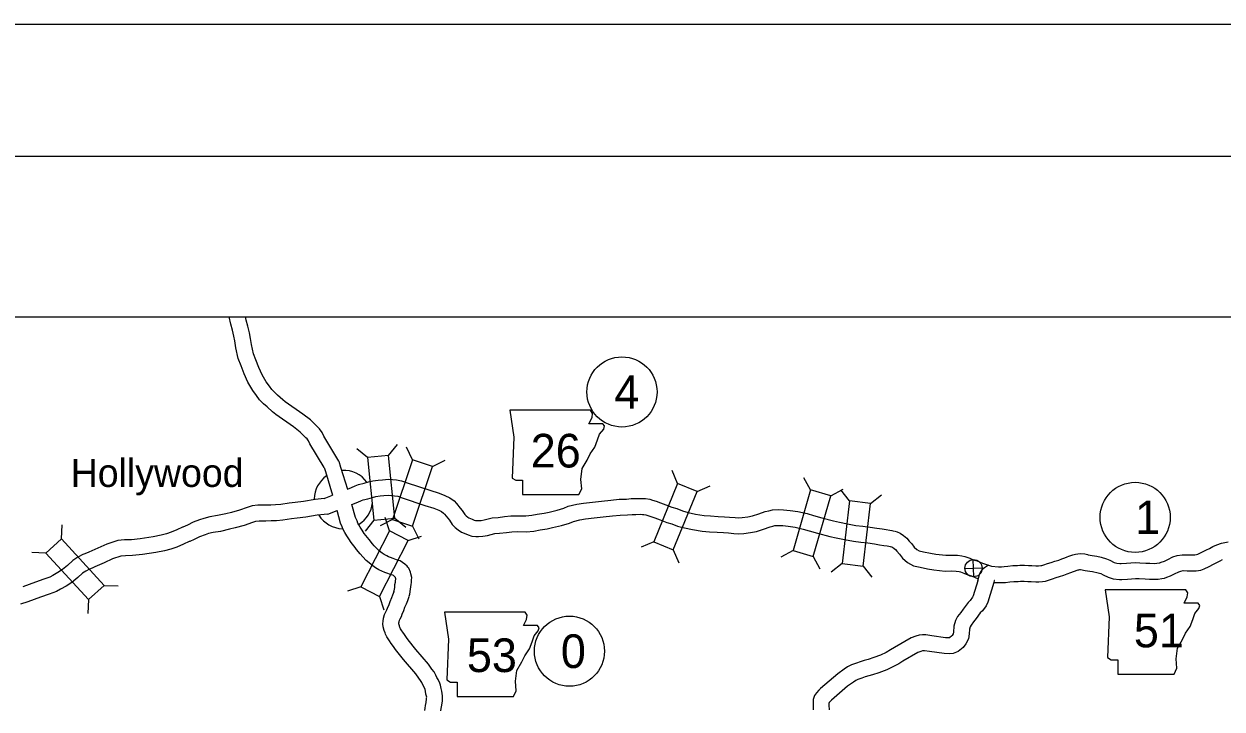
# Model space of a CAD drawing. Extents: x 1369979 to 1371646, y 379997 to 381064.
# Drawn here: x 1370145.5 to 1370321.9, y 380963.2 to 381064.1 of the extents above; entities that cross this region are included whole.
import ezdxf

# ---------------------------------------------------------------- set-up
doc = ezdxf.new("R2010")
doc.units = 0
for name, color, linetype in [('R_Border', 7, 'Continuous'), ('R_Border Notes', 7, 'Continuous'), ('R_No Plot', 7, 'Continuous')]:
    doc.layers.add(name, color=color, linetype=linetype)

msp = doc.modelspace()

# ---------------------------------------------------------------- linework, layer by layer
at = {"layer": 'R_Border'}
msp.add_line((1370040.95, 381044.6), (1371621.85, 381044.6), dxfattribs=at)
at = {"layer": 'R_Border Notes'}
for p, q in [((1370196.09, 381000.26), (1370194.49, 381001.56)), ((1370199.17, 381000.57), (1370200.47, 381002.17)), ((1370202.71, 380999.94), (1370201.79, 381001.79)), ((1370205.65, 380998.96), (1370207.49, 380999.88)), ((1370241.73, 380996.44), (1370240.93, 380998.34)), ((1370244.6, 380995.27), (1370246.5, 380996.08)), ((1370261.31, 380995.48), (1370260.31, 380997.28)), ((1370264.28, 380994.61), (1370266.09, 380995.61)), ((1370267.05, 380993.87), (1370265.77, 380995.49)), ((1370270.12, 380993.51), (1370271.74, 380994.79)), ((1370197.02, 380991.03), (1370195.71, 380989.43)), ((1370199.76, 380991.14), (1370197.92, 380990.22)), ((1370199.31, 380989.47), (1370198.68, 380991.43)), ((1370200.1, 380991.34), (1370201.7, 380990.03)), ((1370151.01, 380988.28), (1370151.1, 380990.35)), ((1370202.7, 380990.16), (1370203.61, 380988.31)), ((1370202.06, 380988.05), (1370204.02, 380988.68)), ((1370238.24, 380987.84), (1370236.34, 380987.04)), ((1370148.72, 380986.2), (1370146.66, 380986.29)), ((1370241.1, 380986.68), (1370241.91, 380984.78)), ((1370258.73, 380986.56), (1370256.92, 380985.57)), ((1370261.7, 380985.7), (1370262.69, 380983.89)), ((1370285.33, 380982.7), (1370285.27, 380985.24)), ((1370265.96, 380984.66), (1370264.34, 380983.38)), ((1370269.03, 380984.29), (1370270.31, 380982.67)), ((1370284.03, 380983.94), (1370286.57, 380984)), ((1370157.27, 380981.44), (1370159.34, 380981.35)), ((1370195.07, 380981.21), (1370193.11, 380980.58)), ((1370154.99, 380979.35), (1370154.9, 380977.29)), ((1370197.82, 380979.8), (1370198.45, 380977.83))]:
    msp.add_line(p, q, dxfattribs=at)
for points in [[(1370189.69, 380998.78), (1370187.6, 381002.28), (1370187.38, 381002.71), (1370187.17, 381002.99), (1370187.01, 381003.18), (1370186.66, 381003.52), (1370186.15, 381004.01), (1370185.16, 381004.76), (1370182.55, 381006.6), (1370182.07, 381006.98), (1370181.28, 381007.7), (1370180.76, 381008.16), (1370180.18, 381008.74), (1370179.72, 381009.38), (1370179.2, 381010.1), (1370178.46, 381011.37), (1370177.92, 381012.6), (1370177.46, 381013.77), (1370177.04, 381014.81), (1370176.66, 381016.42), (1370176.51, 381017.43), (1370176.39, 381018.14), (1370176.17, 381019.02), (1370175.95, 381019.89), (1370175.68, 381020.95)], [(1370191.87, 380999.71), (1370189.65, 381003.42), (1370189.37, 381003.96), (1370189, 381004.46), (1370188.71, 381004.79), (1370188.28, 381005.2), (1370187.68, 381005.79), (1370186.54, 381006.65), (1370183.96, 381008.47), (1370183.59, 381008.77), (1370182.84, 381009.44), (1370182.37, 381009.86), (1370181.97, 381010.27), (1370181.62, 381010.75), (1370181.17, 381011.38), (1370180.55, 381012.43), (1370180.09, 381013.5), (1370179.64, 381014.63), (1370179.28, 381015.52), (1370178.97, 381016.87), (1370178.83, 381017.8), (1370178.68, 381018.62), (1370178.44, 381019.59), (1370178.22, 381020.46), (1370178.1, 381020.95)], [(1370191.87, 380999.71), (1370192.1, 380998.85), (1370193.12, 380995.59)], [(1370189.69, 380998.78), (1370189.86, 380998.19), (1370190.93, 380994.72)], [(1370193.12, 380995.59), (1370193.7, 380995.83), (1370194.23, 380996.09), (1370194.72, 380996.28), (1370195.56, 380996.48), (1370196.23, 380996.66), (1370196.85, 380996.82), (1370197.62, 380996.93), (1370198.26, 380996.99), (1370199.17, 380997.06), (1370200.34, 380996.96), (1370201.09, 380996.83), (1370201.93, 380996.54), (1370205.26, 380995.43), (1370206.63, 380994.99), (1370207.47, 380994.66), (1370208.17, 380994.34), (1370208.81, 380993.86), (1370209.19, 380993.49), (1370209.7, 380992.82), (1370210.03, 380992.44), (1370210.4, 380991.87), (1370210.59, 380991.67), (1370210.83, 380991.47), (1370210.98, 380991.37), (1370211.47, 380991.18), (1370211.76, 380991.05), (1370211.96, 380990.99), (1370212.06, 380990.97), (1370212.28, 380990.99), (1370212.81, 380991), (1370213.25, 380991.09), (1370214.44, 380991.4), (1370215.31, 380991.44), (1370216.25, 380991.56), (1370217.18, 380991.66), (1370218.1, 380991.69), (1370219.36, 380991.69), (1370220.26, 380991.76), (1370221.07, 380991.91), (1370222.08, 380992.09), (1370222.81, 380992.23), (1370224, 380992.52), (1370224.99, 380992.82), (1370225.63, 380993.1), (1370226.91, 380993.4), (1370227.86, 380993.54), (1370229.18, 380993.69), (1370230.52, 380993.85), (1370231.9, 380994), (1370233.14, 380994.12), (1370234.2, 380994.15), (1370234.91, 380994.22), (1370235.53, 380994.24), (1370236.32, 380994.25), (1370236.64, 380994.23), (1370237, 380994.23), (1370237.63, 380994.11), (1370238.04, 380993.98), (1370238.57, 380993.81), (1370239.19, 380993.58), (1370239.98, 380993.29), (1370240.89, 380992.94), (1370241.63, 380992.74), (1370242.47, 380992.4), (1370243.28, 380992.19), (1370244.37, 380991.94), (1370245.62, 380991.73), (1370246.58, 380991.66), (1370247.7, 380991.6), (1370248.64, 380991.54), (1370249.39, 380991.49), (1370250.19, 380991.43), (1370250.67, 380991.4), (1370251.24, 380991.43), (1370252.09, 380991.55), (1370252.76, 380991.67), (1370253.67, 380991.96), (1370254.64, 380992.29), (1370255.15, 380992.43), (1370255.71, 380992.57), (1370256.55, 380992.59), (1370257.34, 380992.58), (1370258.3, 380992.48), (1370259.45, 380992.33), (1370260.83, 380992), (1370261.76, 380991.73), (1370262.98, 380991.38), (1370264.69, 380990.92), (1370265.56, 380990.72), (1370266.73, 380990.51), (1370267.99, 380990.27), (1370269, 380990.15), (1370270.06, 380990.01), (1370271.06, 380989.87), (1370271.83, 380989.74), (1370272.45, 380989.65), (1370272.96, 380989.57), (1370273.28, 380989.52), (1370273.61, 380989.44)], [(1370189.67, 380994.23), (1370188.35, 380994.09), (1370186.65, 380993.79), (1370185.41, 380993.64), (1370184.55, 380993.54), (1370183.32, 380993.35), (1370182.53, 380993.28), (1370181.85, 380993.26), (1370181.09, 380993.26), (1370180.55, 380993.26), (1370179.94, 380993.25), (1370179.07, 380993.13), (1370178.37, 380992.9), (1370177.22, 380992.49), (1370176.02, 380992.19), (1370175.19, 380991.98), (1370174, 380991.7), (1370172.87, 380991.54), (1370171.97, 380991.3), (1370171.35, 380991.08), (1370170.41, 380990.73), (1370169.58, 380990.32), (1370168.88, 380990.03), (1370168.81, 380990)], [(1370189.67, 380994.23), (1370190.93, 380994.72)], [(1370193.78, 380993.33), (1370194.66, 380993.69), (1370195.18, 380993.94), (1370195.42, 380994.04), (1370196.14, 380994.2), (1370196.82, 380994.39), (1370197.31, 380994.51), (1370197.91, 380994.6), (1370198.47, 380994.66), (1370199.16, 380994.71), (1370200.04, 380994.63), (1370200.51, 380994.55), (1370201.18, 380994.32), (1370204.53, 380993.2), (1370205.85, 380992.78), (1370206.56, 380992.5), (1370206.96, 380992.32), (1370207.27, 380992.09), (1370207.43, 380991.93), (1370207.89, 380991.33), (1370208.16, 380991.02), (1370208.55, 380990.41), (1370209, 380989.94), (1370209.43, 380989.6), (1370209.89, 380989.28), (1370210.55, 380989.03), (1370210.91, 380988.86), (1370211.45, 380988.69), (1370212, 380988.62), (1370212.41, 380988.65), (1370213.05, 380988.66), (1370213.76, 380988.8), (1370214.8, 380989.07), (1370215.52, 380989.1), (1370216.52, 380989.24), (1370217.34, 380989.32), (1370218.14, 380989.35), (1370219.45, 380989.34), (1370220.56, 380989.43), (1370221.48, 380989.6), (1370222.52, 380989.78), (1370223.31, 380989.95), (1370224.61, 380990.25), (1370225.8, 380990.61), (1370226.38, 380990.86), (1370227.35, 380991.1), (1370228.16, 380991.21), (1370229.45, 380991.36), (1370230.79, 380991.52), (1370232.14, 380991.67), (1370233.29, 380991.78), (1370234.34, 380991.81), (1370235.05, 380991.88), (1370235.58, 380991.89), (1370236.28, 380991.9), (1370236.57, 380991.89), (1370236.75, 380991.89), (1370237.06, 380991.83), (1370237.34, 380991.74), (1370237.81, 380991.59), (1370238.38, 380991.38), (1370239.16, 380991.1), (1370240.16, 380990.71), (1370240.88, 380990.51), (1370241.73, 380990.17), (1370242.73, 380989.91), (1370243.92, 380989.64), (1370245.33, 380989.41), (1370246.43, 380989.32), (1370247.56, 380989.26), (1370248.48, 380989.2), (1370249.23, 380989.16), (1370250.03, 380989.09), (1370250.65, 380989.05), (1370251.46, 380989.09), (1370252.47, 380989.24), (1370253.33, 380989.39), (1370254.4, 380989.73), (1370255.34, 380990.05), (1370255.75, 380990.17), (1370256.03, 380990.24), (1370256.56, 380990.25), (1370257.21, 380990.24), (1370258.03, 380990.15), (1370259.02, 380990.03), (1370260.23, 380989.73), (1370261.12, 380989.48), (1370262.35, 380989.12), (1370264.12, 380988.64), (1370265.09, 380988.42), (1370266.3, 380988.2), (1370267.63, 380987.95), (1370268.7, 380987.82), (1370269.74, 380987.69), (1370270.71, 380987.55), (1370271.47, 380987.42), (1370272.1, 380987.33), (1370272.61, 380987.25), (1370272.83, 380987.22), (1370273.09, 380987.16)], [(1370190.23, 380991.94), (1370191.59, 380992.46)], [(1370199.96, 380980.49), (1370200, 380980.62), (1370200.07, 380981.14), (1370200.11, 380981.56), (1370200.18, 380981.91), (1370200.2, 380982.13), (1370200.22, 380982.35), (1370200.22, 380982.38), (1370200.18, 380982.57), (1370200.17, 380982.62), (1370200.16, 380982.63), (1370200.11, 380982.72), (1370199.89, 380982.87), (1370199.81, 380982.92), (1370199.57, 380983), (1370199.08, 380983.18), (1370198.63, 380983.32), (1370198.16, 380983.52), (1370197.75, 380983.73), (1370197.25, 380984.04), (1370196.87, 380984.31), (1370196.3, 380984.74), (1370195.88, 380985.12), (1370195.36, 380985.62), (1370194.97, 380986.08), (1370194.47, 380986.73), (1370194.23, 380987.01), (1370193.65, 380987.75), (1370193.31, 380988.31), (1370193.03, 380988.72), (1370192.72, 380989.24), (1370192.5, 380989.68), (1370192.36, 380990.04), (1370192.09, 380990.62), (1370191.59, 380992.46)], [(1370202.22, 380979.84), (1370202.3, 380980.14), (1370202.4, 380980.88), (1370202.43, 380981.22), (1370202.5, 380981.56), (1370202.53, 380981.88), (1370202.56, 380982.2), (1370202.58, 380982.61), (1370202.46, 380983.15), (1370202.39, 380983.39), (1370202.15, 380983.96), (1370202, 380984.12), (1370201.9, 380984.27), (1370201.58, 380984.56), (1370201.23, 380984.79), (1370200.89, 380985.04), (1370200.33, 380985.22), (1370199.84, 380985.39), (1370199.45, 380985.52), (1370199.15, 380985.65), (1370198.91, 380985.77), (1370198.54, 380986), (1370198.25, 380986.2), (1370197.8, 380986.54), (1370197.48, 380986.83), (1370197.06, 380987.24), (1370196.78, 380987.56), (1370196.3, 380988.19), (1370196.06, 380988.48), (1370195.58, 380989.08), (1370195.29, 380989.58), (1370195, 380989.99), (1370194.77, 380990.37), (1370194.65, 380990.62), (1370194.53, 380990.94), (1370194.3, 380991.43), (1370193.78, 380993.33)], [(1370190.23, 380991.94), (1370188.68, 380991.77), (1370187, 380991.47), (1370185.69, 380991.32), (1370184.86, 380991.22), (1370183.61, 380991.03), (1370182.67, 380990.94), (1370181.88, 380990.92), (1370181.1, 380990.91), (1370180.56, 380990.91), (1370180.11, 380990.91), (1370179.6, 380990.84), (1370179.13, 380990.69), (1370177.9, 380990.24), (1370176.59, 380989.92), (1370175.75, 380989.7), (1370174.43, 380989.39), (1370173.34, 380989.24), (1370172.66, 380989.06), (1370172.16, 380988.88), (1370171.34, 380988.57), (1370170.54, 380988.18), (1370169.92, 380987.92)], [(1370168.81, 380990), (1370168, 380989.63), (1370167.16, 380989.26), (1370166.46, 380989.02), (1370165.67, 380988.83), (1370164.52, 380988.6), (1370162.6, 380988.31), (1370161.31, 380988.16), (1370160.28, 380988.12), (1370159.31, 380988.03), (1370157.67, 380987.52), (1370156.35, 380986.9), (1370155.02, 380986.32), (1370154.45, 380986.09)], [(1370273.7, 380989.42), (1370274.08, 380989.31), (1370274.48, 380989.11), (1370275.01, 380988.79), (1370275.48, 380988.39), (1370275.84, 380987.97), (1370276.2, 380987.53), (1370276.57, 380987.07), (1370276.93, 380986.74), (1370277.31, 380986.53), (1370277.95, 380986.39), (1370278.96, 380986.17), (1370279.76, 380986.04), (1370281.22, 380985.89), (1370282.1, 380985.9), (1370282.95, 380985.87), (1370283.6, 380985.79), (1370284.04, 380985.68), (1370284.75, 380985.44), (1370285.26, 380985.22), (1370285.84, 380985.05), (1370286.61, 380984.69)], [(1370169.92, 380987.92), (1370169.81, 380987.88), (1370168.96, 380987.49), (1370168.01, 380987.07), (1370167.11, 380986.77), (1370166.17, 380986.54), (1370164.92, 380986.29), (1370162.92, 380985.99), (1370161.49, 380985.82), (1370160.42, 380985.78), (1370159.77, 380985.72), (1370158.53, 380985.33), (1370157.31, 380984.76), (1370155.93, 380984.16), (1370155.51, 380983.99)], [(1370273.01, 380987.18), (1370273.23, 380987.11), (1370273.37, 380987.04), (1370273.64, 380986.89), (1370273.8, 380986.74), (1370274.03, 380986.47), (1370274.38, 380986.04), (1370274.86, 380985.46), (1370275.56, 380984.82), (1370276.46, 380984.33), (1370277.44, 380984.1), (1370278.52, 380983.86), (1370279.46, 380983.71), (1370281.11, 380983.55), (1370282.07, 380983.56), (1370282.76, 380983.53), (1370283.19, 380983.48), (1370283.4, 380983.43), (1370283.89, 380983.26), (1370284.45, 380983.01), (1370285.02, 380982.84), (1370285.99, 380982.4)], [(1370288.99, 380984.18), (1370289, 380984.18), (1370289.42, 380984.19), (1370289.81, 380984.21), (1370290.37, 380984.28), (1370291.08, 380984.37), (1370291.8, 380984.37), (1370292.14, 380984.39), (1370292.8, 380984.39), (1370293.4, 380984.36), (1370293.88, 380984.34), (1370294.5, 380984.31), (1370294.86, 380984.32), (1370295.2, 380984.34), (1370295.36, 380984.37), (1370295.64, 380984.45), (1370296.19, 380984.64), (1370296.72, 380984.82), (1370297.25, 380984.99), (1370297.87, 380985.17), (1370298.31, 380985.33), (1370298.76, 380985.49), (1370299.07, 380985.62), (1370299.34, 380985.75), (1370299.9, 380985.92), (1370300.1, 380985.97), (1370300.34, 380986.04), (1370300.67, 380986.09), (1370301.06, 380986.13), (1370301.71, 380986.06), (1370302.09, 380985.96), (1370302.2, 380985.93), (1370302.76, 380985.84), (1370303.11, 380985.8), (1370303.44, 380985.76), (1370304.09, 380985.61), (1370304.87, 380985.36), (1370305.36, 380985.14), (1370306.01, 380984.83), (1370306.39, 380984.7), (1370306.84, 380984.65), (1370307.02, 380984.66), (1370307.81, 380984.69), (1370309.08, 380984.8), (1370309.78, 380984.77), (1370310.68, 380984.72), (1370311.27, 380984.7), (1370311.92, 380984.68), (1370312.3, 380984.7), (1370312.62, 380984.74), (1370312.75, 380984.77), (1370312.94, 380984.84), (1370313.4, 380985.02), (1370313.89, 380985.24), (1370314.64, 380985.62), (1370315.27, 380985.82), (1370316, 380985.95), (1370316.8, 380985.94), (1370317.5, 380985.93), (1370317.9, 380985.91), (1370318.15, 380985.96), (1370318.34, 380986.03), (1370318.92, 380986.32), (1370319.59, 380986.67), (1370320.05, 380986.89), (1370320.55, 380987.16), (1370321.11, 380987.43), (1370321.8, 380987.64), (1370322.8, 380987.85)], [(1370154.45, 380986.09), (1370154.15, 380985.96), (1370153.41, 380985.59), (1370152.67, 380985.11), (1370151.88, 380984.38), (1370151.15, 380983.77), (1370150.47, 380983.34), (1370149.73, 380982.9), (1370149.31, 380982.67), (1370148.4, 380982.33), (1370147.16, 380981.89), (1370145.3, 380981.24)], [(1370288.29, 380981.86), (1370288.97, 380981.84), (1370289.5, 380981.84), (1370290.03, 380981.87), (1370290.67, 380981.96), (1370291.23, 380982.03), (1370291.86, 380982.03), (1370292.2, 380982.05), (1370292.74, 380982.05), (1370293.28, 380982.02), (1370293.78, 380981.99), (1370294.47, 380981.97), (1370294.94, 380981.97), (1370295.47, 380982.01), (1370295.89, 380982.08), (1370296.36, 380982.22), (1370296.95, 380982.42), (1370297.46, 380982.59), (1370297.95, 380982.75), (1370298.61, 380982.95), (1370299.1, 380983.13), (1370299.61, 380983.31), (1370300.01, 380983.48), (1370300.17, 380983.55), (1370300.54, 380983.67), (1370300.72, 380983.71), (1370300.83, 380983.74), (1370300.96, 380983.76), (1370301.07, 380983.77), (1370301.28, 380983.75), (1370301.49, 380983.69), (1370301.74, 380983.63), (1370302.44, 380983.52), (1370302.82, 380983.48), (1370303.03, 380983.45), (1370303.47, 380983.35), (1370304.03, 380983.17), (1370304.38, 380983.01), (1370305.12, 380982.65), (1370305.88, 380982.4), (1370306.78, 380982.29), (1370307.15, 380982.32), (1370307.96, 380982.35), (1370309.13, 380982.45), (1370309.68, 380982.43), (1370310.57, 380982.38), (1370311.19, 380982.36), (1370311.94, 380982.34), (1370312.49, 380982.36), (1370313.01, 380982.43), (1370313.4, 380982.51), (1370313.75, 380982.64), (1370314.32, 380982.86), (1370314.9, 380983.13), (1370315.53, 380983.44), (1370315.85, 380983.54), (1370316.19, 380983.61), (1370316.75, 380983.6), (1370317.43, 380983.58), (1370318.07, 380983.56), (1370318.75, 380983.68), (1370319.28, 380983.87), (1370319.99, 380984.24), (1370320.63, 380984.57), (1370321.12, 380984.81), (1370321.62, 380985.07), (1370321.96, 380985.24)], [(1370155.51, 380983.99), (1370155.13, 380983.83), (1370154.59, 380983.55), (1370154.11, 380983.25), (1370153.43, 380982.62), (1370152.54, 380981.88), (1370151.69, 380981.34), (1370150.88, 380980.86), (1370150.28, 380980.54), (1370149.21, 380980.13), (1370147.94, 380979.68), (1370146.05, 380979.01), (1370144.96, 380978.66)], [(1370287.51, 380984.42), (1370286.94, 380984.02), (1370286.73, 380983.87), (1370286.49, 380983.64), (1370286.3, 380983.34), (1370286.13, 380983), (1370285.9, 380982.05)], [(1370286.61, 380984.69), (1370287.96, 380984.29)], [(1370287.96, 380984.29), (1370288.99, 380984.18)], [(1370285.92, 380982.11), (1370285.24, 380979.88), (1370285.14, 380979.68), (1370284.81, 380979.22), (1370284.52, 380978.93), (1370283.79, 380977.96), (1370283.43, 380977.46), (1370282.96, 380976.86), (1370282.64, 380976.26), (1370282.39, 380975.42), (1370282.33, 380974.56), (1370282.29, 380974.32), (1370282.17, 380974.08), (1370282.06, 380973.94), (1370281.82, 380973.75), (1370281.76, 380973.73), (1370281.68, 380973.72), (1370281.17, 380973.73), (1370279.18, 380974.03), (1370278.28, 380974.15), (1370277.79, 380974.16), (1370277.32, 380974.11), (1370276.81, 380973.95), (1370276.11, 380973.7), (1370273.67, 380972.3), (1370273.08, 380971.93), (1370272.44, 380971.58), (1370271.62, 380971.18), (1370270.6, 380970.8), (1370269.78, 380970.54), (1370269.22, 380970.37), (1370268.62, 380970.19), (1370268.07, 380970.01), (1370267.33, 380969.74), (1370266.76, 380969.46), (1370266.25, 380969.1), (1370265.31, 380968.44), (1370262.77, 380966.24), (1370262.52, 380966), (1370262.17, 380965.64), (1370261.88, 380965.25), (1370261.71, 380964.64), (1370261.67, 380964.14), (1370261.68, 380963.76), (1370261.69, 380963.14)], [(1370288.29, 380981.86), (1370287.42, 380978.98), (1370287.14, 380978.45), (1370286.6, 380977.7), (1370286.29, 380977.39), (1370285.67, 380976.56), (1370285.3, 380976.05), (1370284.93, 380975.58), (1370284.82, 380975.36), (1370284.71, 380975), (1370284.67, 380974.29), (1370284.54, 380973.58), (1370284.16, 380972.83), (1370283.76, 380972.29), (1370283.02, 380971.7), (1370282.28, 380971.41), (1370281.73, 380971.38), (1370280.97, 380971.39), (1370278.84, 380971.71), (1370278.1, 380971.81), (1370277.91, 380971.82), (1370277.8, 380971.8), (1370277.54, 380971.73), (1370277.1, 380971.56), (1370274.88, 380970.3), (1370274.28, 380969.91), (1370273.51, 380969.5), (1370272.55, 380969.03), (1370271.37, 380968.58), (1370270.45, 380968.29), (1370269.89, 380968.13), (1370269.33, 380967.96), (1370268.84, 380967.8), (1370268.25, 380967.58), (1370267.96, 380967.44), (1370267.61, 380967.19), (1370266.75, 380966.59), (1370264.37, 380964.53), (1370264.2, 380964.36), (1370264.03, 380964.18), (1370264.02, 380964.07), (1370264.02, 380963.79), (1370264.03, 380963.14)], [(1370288.4, 380982.18), (1370288.34, 380982.14), (1370288.27, 380981.86)], [(1370204.49, 380963.03), (1370204.54, 380963.35), (1370204.62, 380963.75), (1370204.69, 380964.18), (1370204.76, 380964.74), (1370204.77, 380964.87), (1370204.78, 380964.96), (1370204.68, 380965.43), (1370204.61, 380965.89), (1370204.57, 380966.12), (1370204.57, 380966.12), (1370204.4, 380966.48), (1370204.21, 380966.8), (1370204.06, 380967.13), (1370203.89, 380967.42), (1370203.64, 380967.77), (1370203.2, 380968.41), (1370201.38, 380970.52), (1370200.18, 380972.01), (1370199.89, 380972.42), (1370199.56, 380972.89), (1370199.32, 380973.26), (1370199.2, 380973.43), (1370198.92, 380973.87), (1370198.72, 380974.26), (1370198.65, 380974.46), (1370198.53, 380974.79), (1370198.38, 380975.36), (1370198.34, 380975.76), (1370198.36, 380976.15), (1370198.42, 380976.59), (1370198.58, 380977.13), (1370198.76, 380977.55), (1370198.93, 380977.86), (1370199.02, 380978.1), (1370199.24, 380978.6), (1370199.39, 380979.06), (1370199.65, 380979.63), (1370199.81, 380980.03), (1370199.98, 380980.55)], [(1370206.85, 380962.95), (1370206.92, 380963.33), (1370207.01, 380963.83), (1370207.09, 380964.46), (1370207.12, 380964.71), (1370207.12, 380965.17), (1370206.99, 380965.85), (1370206.92, 380966.28), (1370206.84, 380966.76), (1370206.72, 380967.06), (1370206.48, 380967.56), (1370206.29, 380967.9), (1370206.13, 380968.24), (1370205.86, 380968.7), (1370205.56, 380969.11), (1370205.06, 380969.85), (1370203.18, 380972.02), (1370202.05, 380973.43), (1370201.8, 380973.78), (1370201.5, 380974.2), (1370201.28, 380974.56), (1370201.14, 380974.75), (1370200.95, 380975.04), (1370200.87, 380975.21), (1370200.85, 380975.26), (1370200.77, 380975.48), (1370200.69, 380975.79), (1370200.69, 380975.82), (1370200.69, 380975.92), (1370200.72, 380976.09), (1370200.79, 380976.34), (1370200.87, 380976.53), (1370201.05, 380976.86), (1370201.19, 380977.19), (1370201.43, 380977.76), (1370201.58, 380978.21), (1370201.81, 380978.72), (1370202.01, 380979.23), (1370202.2, 380979.79)]]:
    msp.add_lwpolyline(points, dxfattribs=at)
for points in [[(1370217.03, 381007.22), (1370217.63, 381003.26), (1370217.37, 380997.24), (1370217.89, 380996.91), (1370218.89, 380996.91), (1370218.89, 380994.8), (1370227.21, 380994.8), (1370227.61, 380995.66), (1370227.48, 380997.04), (1370227.67, 380998.63), (1370228.4, 380999.88), (1370228.86, 381000.81), (1370229.53, 381001.8), (1370229.92, 381002.86), (1370230.25, 381003.72), (1370230.85, 381004.44), (1370230.98, 381004.91), (1370230.71, 381005.24), (1370228.67, 381005.24), (1370229.13, 381006.16), (1370229.19, 381006.76), (1370228.92, 381007.21)], [(1370196.09, 381000.26), (1370197.02, 380991.03), (1370200.1, 380991.34), (1370199.17, 381000.57)], [(1370202.7, 380990.16), (1370205.65, 380998.96), (1370202.71, 380999.94), (1370199.76, 380991.14)], [(1370241.1, 380986.68), (1370244.6, 380995.27), (1370241.73, 380996.44), (1370238.24, 380987.84)], [(1370261.7, 380985.7), (1370264.28, 380994.61), (1370261.31, 380995.48), (1370258.73, 380986.56)], [(1370269.03, 380984.29), (1370270.12, 380993.51), (1370267.05, 380993.87), (1370265.96, 380984.66)], [(1370197.82, 380979.8), (1370202.06, 380988.05), (1370199.31, 380989.47), (1370195.07, 380981.21)], [(1370157.27, 380981.44), (1370151.01, 380988.28), (1370148.72, 380986.2), (1370154.99, 380979.35)], [(1370304.69, 380980.8), (1370305.28, 380976.83), (1370305.02, 380970.82), (1370305.55, 380970.49), (1370306.54, 380970.49), (1370306.54, 380968.38), (1370314.86, 380968.38), (1370315.26, 380969.23), (1370315.13, 380970.62), (1370315.33, 380972.21), (1370316.05, 380973.46), (1370316.52, 380974.39), (1370317.18, 380975.38), (1370317.57, 380976.44), (1370317.9, 380977.3), (1370318.5, 380978.02), (1370318.63, 380978.49), (1370318.37, 380978.82), (1370316.32, 380978.82), (1370316.78, 380979.74), (1370316.85, 380980.34), (1370316.57, 380980.79)], [(1370207.41, 380977.5), (1370208, 380973.54), (1370207.74, 380967.52), (1370208.27, 380967.19), (1370209.26, 380967.19), (1370209.26, 380965.08), (1370217.58, 380965.08), (1370217.98, 380965.94), (1370217.85, 380967.32), (1370218.05, 380968.91), (1370218.77, 380970.17), (1370219.24, 380971.09), (1370219.9, 380972.08), (1370220.29, 380973.14), (1370220.62, 380974), (1370221.22, 380974.73), (1370221.35, 380975.19), (1370221.09, 380975.52), (1370219.04, 380975.52), (1370219.5, 380976.44), (1370219.57, 380977.04), (1370219.29, 380977.5)]]:
    msp.add_lwpolyline(points, close=True, dxfattribs=at)
for centre, radius in [((1370233.54, 381009.91), 5.16), ((1370309.1, 380991.45), 5.16), ((1370285.3, 380983.97), 1.27), ((1370225.8, 380971.75), 5.16)]:
    msp.add_circle(centre, radius, dxfattribs=at)
for start, end in [(36.5633, 92.1915), (125.5937, 178.7511), (302.7387, 353.3917), (212.5565, 267.8216)]:
    msp.add_arc((1370192.53, 380994.07), 4.3, start, end, dxfattribs=at)
at = {"layer": 'R_No Plot'}
msp.add_line((1369978.95, 381064.07), (1371645.61, 381064.07), dxfattribs=at)
for points in [[(1369978.91, 381064.07), (1371645.61, 381064.07), (1371645.61, 379997.39), (1369978.91, 379997.39)], [(1370052.8, 381020.95), (1370474.58, 381020.95), (1370474.58, 380650.53), (1370052.8, 380650.53)]]:
    msp.add_lwpolyline(points, close=True, dxfattribs=at)

# ---------------------------------------------------------------- texts
at = {"layer": 'R_Border Notes'}
for s, height, p in [('4', 4.95, (1370232.43, 381007.43)), ('26', 4.95, (1370220.1, 380998.79)), ('Hollywood', 4.125, (1370152.37, 380995.93)), ('1', 4.95, (1370309.1, 380988.98)), ('51', 4.95, (1370308.91, 380972.32)), ('53', 4.95, (1370210.7, 380968.68)), ('0', 4.95, (1370224.54, 380969.28))]:
    msp.add_text(s, height=height, dxfattribs=at).set_placement(p)

doc.saveas('drawing.dxf')
